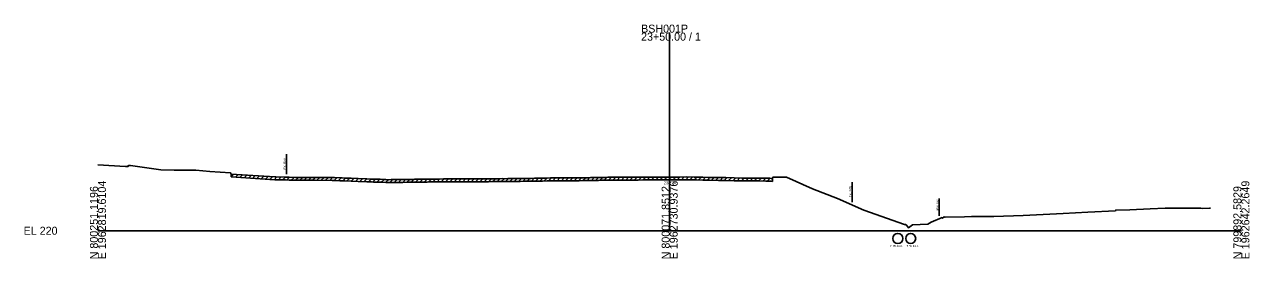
# Model space of a CAD drawing. Extents: x -26 to 1403, y -10 to 19587.
# Drawn here: x -25.7 to 402.8, y 7490.3 to 7572 of the extents above; entities that cross this region are included whole.
import ezdxf

# ---------------------------------------------------------------- set-up
doc = ezdxf.new("R2010")
doc.units = 0
for name, color, linetype in [('Default', 7, 'Continuous'), ('RD_EX_H2O', 7, 'Continuous'), ('RD_GPK_XS_Cell', 7, 'Continuous'), ('RD_XS_ExGround', 7, 'Continuous'), ('RD_XS_ExPaveRet', 7, 'Continuous'), ('RD_XS_ExRW', 7, 'Continuous'), ('RD_XS_NewRW', 7, 'Continuous'), ('RD_XS_TX_Elev_EX', 7, 'Continuous')]:
    doc.layers.add(name, color=color, linetype=linetype)

msp = doc.modelspace()

# ---------------------------------------------------------------- linework, layer by layer
at = {"layer": 'RD_EX_H2O'}
for centre in [(279.81, 7497.29), (284.31, 7497.29)]:
    msp.add_circle(centre, 1.75, dxfattribs=at)
at = {"layer": 'RD_GPK_XS_Cell'}
for p, q in [((200, 7500), (200, 7569.2)), ((0, 7500), (200, 7500)), ((200, 7500), (400, 7500))]:
    msp.add_line(p, q, dxfattribs=at)
at = {"layer": 'RD_XS_ExGround'}
msp.add_lwpolyline([(0, 7523.07), (9.67, 7522.48), (10.07, 7522.44), (10.48, 7522.4), (10.7, 7522.84), (11.4, 7522.77), (21.95, 7521.29), (26.69, 7521.14), (30.14, 7521.2), (34.27, 7521.13), (39.17, 7520.73), (46.42, 7520.22), (46.61, 7519.77), (61.88, 7518.82), (62.21, 7518.8), (65.56, 7518.76), (66.95, 7518.68), (69.11, 7518.63), (69.55, 7518.64), (72.11, 7518.65), (73.34, 7518.65), (73.64, 7518.64), (75.95, 7518.63), (81.95, 7518.59), (82.76, 7518.55), (84.58, 7518.48), (85.44, 7518.44), (86.42, 7518.41), (88.53, 7518.33), (91.02, 7518.21), (94.07, 7518.1), (95.65, 7518.05), (96.45, 7518.02), (98.73, 7517.96), (99.76, 7517.93), (100.76, 7517.86), (101.44, 7517.82), (101.8, 7517.83), (102.52, 7517.84), (103.98, 7517.85), (104.6, 7517.86), (105.34, 7517.87), (106.7, 7517.89), (108.12, 7517.92), (108.59, 7517.93), (109.56, 7517.94), (110.46, 7517.95), (110.91, 7517.96), (112.23, 7517.98), (113.71, 7518), (114.2, 7518.01), (115.18, 7518.02), (116.06, 7518.03), (116.49, 7518.04), (117.93, 7518.06), (119.28, 7518.07), (120.84, 7518.09), (121.67, 7518.09), (122.08, 7518.1), (123.28, 7518.1), (124.87, 7518.1), (125.47, 7518.09), (126.49, 7518.1), (127.26, 7518.09), (127.65, 7518.09), (128.58, 7518.1), (129.9, 7518.1), (130.93, 7518.1), (131.6, 7518.11), (133.16, 7518.11), (133.86, 7518.11), (135.51, 7518.12), (136.02, 7518.13), (136.59, 7518.12), (137.75, 7518.15), (138.8, 7518.16), (140.31, 7518.16), (141.59, 7518.19), (142.18, 7518.18), (143.4, 7518.21), (144.06, 7518.21), (144.38, 7518.22), (145.34, 7518.23), (146.97, 7518.23), (147.74, 7518.23), (148.96, 7518.26), (149.62, 7518.26), (149.93, 7518.27), (151.51, 7518.3), (152.7, 7518.31), (154.67, 7518.35), (155.53, 7518.36), (157.14, 7518.4), (158.35, 7518.43), (160.36, 7518.45), (161.07, 7518.45), (162.72, 7518.44), (163.9, 7518.45), (164.99, 7518.45), (166.58, 7518.46), (167.16, 7518.45), (167.54, 7518.45), (168.32, 7518.47), (169.5, 7518.51), (171.63, 7518.53), (172.28, 7518.54), (172.91, 7518.55), (175.07, 7518.59), (175.8, 7518.61), (177.27, 7518.64), (177.85, 7518.65), (178.42, 7518.66), (180.61, 7518.69), (182.87, 7518.69), (183.41, 7518.69), (185.1, 7518.7), (186.2, 7518.7), (188.48, 7518.71), (188.98, 7518.71), (190.68, 7518.74), (191.77, 7518.75), (192.57, 7518.75), (194.16, 7518.76), (194.56, 7518.76), (194.94, 7518.76), (197.31, 7518.75), (198.16, 7518.75), (200.19, 7518.74), (200.5, 7518.75), (202.93, 7518.76), (206.04, 7518.78), (208.52, 7518.76), (209.37, 7518.74), (211.55, 7518.7), (214.11, 7518.64), (217.05, 7518.6), (219.68, 7518.55), (222.56, 7518.47), (225.24, 7518.42), (228.02, 7518.38), (230.61, 7518.38), (230.95, 7518.38), (233.61, 7518.34), (235.02, 7518.33), (235.49, 7518.28), (235.93, 7518.25), (236.01, 7518.28), (236.11, 7518.73), (237.44, 7518.73), (240.89, 7518.74), (249.98, 7514.65), (258.73, 7511.22), (267.93, 7507.24), (282.15, 7502.2), (282.48, 7502.18), (282.91, 7501.78), (283.59, 7500.97), (284.94, 7502.04), (290.31, 7502.26), (291.44, 7503), (295.36, 7504.62), (295.46, 7504.37), (296.06, 7504.8), (296.4, 7504.79), (303.15, 7504.89), (305.55, 7504.92), (310.45, 7504.94), (313.44, 7504.94), (323.62, 7505.37), (337.61, 7506.07), (346.25, 7506.48), (355.94, 7507), (356.04, 7507.24), (360.97, 7507.33), (368.05, 7507.67), (373.35, 7507.83), (385.79, 7507.85), (386.56, 7507.78), (388.82, 7507.86), (389.16, 7507.92)], dxfattribs=at)
at = {"layer": 'RD_XS_ExPaveRet'}
for p, q in [((46.61, 7518.77), (46.61, 7519.77)), ((46.61, 7518.77), (47.55, 7519.71)), ((46.61, 7518.77), (61.88, 7517.82)), ((48.11, 7518.67), (49.05, 7519.61)), ((49.61, 7518.58), (50.55, 7519.52)), ((51.11, 7518.49), (52.05, 7519.43)), ((52.61, 7518.39), (53.55, 7519.33)), ((54.11, 7518.3), (55.05, 7519.24)), ((55.61, 7518.21), (56.55, 7519.15)), ((57.11, 7518.11), (58.05, 7519.06)), ((58.61, 7518.02), (59.55, 7518.96)), ((60.11, 7517.93), (61.05, 7518.87)), ((61.61, 7517.83), (62.57, 7518.79)), ((61.88, 7517.82), (62.21, 7517.8)), ((62.21, 7517.8), (65.56, 7517.76)), ((63.11, 7517.79), (64.1, 7518.78)), ((64.61, 7517.77), (65.6, 7518.76)), ((65.56, 7517.76), (66.95, 7517.68)), ((66.11, 7517.73), (67.06, 7518.68)), ((66.95, 7517.68), (69.11, 7517.63)), ((67.61, 7517.66), (68.59, 7518.64)), ((69.11, 7517.63), (70.12, 7518.64)), ((69.11, 7517.63), (69.55, 7517.64)), ((69.55, 7517.64), (72.11, 7517.65)), ((70.61, 7517.64), (71.62, 7518.65)), ((72.11, 7517.65), (73.11, 7518.65)), ((72.11, 7517.65), (73.34, 7517.65)), ((73.34, 7517.65), (73.64, 7517.64)), ((73.61, 7517.65), (74.61, 7518.64)), ((73.64, 7517.64), (75.95, 7517.63)), ((75.11, 7517.64), (76.11, 7518.63)), ((75.95, 7517.63), (81.95, 7517.59)), ((76.61, 7517.63), (77.61, 7518.62)), ((78.11, 7517.62), (79.11, 7518.61)), ((79.61, 7517.61), (80.61, 7518.6)), ((81.11, 7517.6), (82.1, 7518.58)), ((81.95, 7517.59), (82.76, 7517.55)), ((82.61, 7517.56), (83.57, 7518.52)), ((82.76, 7517.55), (84.58, 7517.48)), ((84.11, 7517.5), (85.07, 7518.46)), ((84.58, 7517.48), (85.44, 7517.44)), ((85.44, 7517.44), (86.42, 7517.41)), ((85.61, 7517.44), (86.58, 7518.4)), ((86.42, 7517.41), (88.53, 7517.33)), ((87.11, 7517.38), (88.08, 7518.35)), ((88.53, 7517.33), (91.02, 7517.21)), ((88.61, 7517.32), (89.57, 7518.28)), ((90.11, 7517.25), (91.07, 7518.21)), ((91.02, 7517.21), (94.07, 7517.1)), ((91.61, 7517.19), (92.58, 7518.15)), ((93.11, 7517.14), (94.08, 7518.1)), ((94.07, 7517.1), (95.65, 7517.05)), ((94.61, 7517.08), (95.58, 7518.05)), ((95.65, 7517.05), (96.45, 7517.02)), ((96.11, 7517.03), (97.08, 7518.01)), ((96.45, 7517.02), (98.73, 7516.96)), ((97.61, 7516.99), (98.58, 7517.96)), ((98.73, 7516.96), (99.76, 7516.93)), ((99.11, 7516.95), (100.07, 7517.9)), ((99.76, 7516.93), (100.76, 7516.86)), ((100.61, 7516.87), (101.57, 7517.83)), ((100.76, 7516.86), (101.44, 7516.82)), ((101.44, 7516.82), (101.8, 7516.83)), ((101.8, 7516.83), (102.52, 7516.84)), ((102.11, 7516.84), (103.12, 7517.85)), ((102.52, 7516.84), (103.98, 7516.85)), ((103.61, 7516.85), (104.62, 7517.86)), ((103.98, 7516.85), (104.6, 7516.86)), ((104.6, 7516.86), (105.34, 7516.87)), ((105.11, 7516.86), (106.13, 7517.88)), ((105.34, 7516.87), (106.7, 7516.89)), ((106.61, 7516.89), (107.63, 7517.91)), ((106.7, 7516.89), (108.12, 7516.92)), ((108.11, 7516.92), (109.13, 7517.94)), ((108.12, 7516.92), (108.59, 7516.93)), ((108.59, 7516.93), (109.56, 7516.94)), ((109.56, 7516.94), (110.46, 7516.95)), ((109.61, 7516.94), (110.63, 7517.96)), ((110.46, 7516.95), (110.91, 7516.96)), ((110.91, 7516.96), (112.23, 7516.98)), ((111.11, 7516.96), (112.13, 7517.98)), ((112.23, 7516.98), (113.71, 7517)), ((112.61, 7516.98), (113.63, 7518)), ((113.71, 7517), (114.2, 7517.01)), ((114.11, 7517), (115.13, 7518.02)), ((114.2, 7517.01), (115.18, 7517.02)), ((115.18, 7517.02), (116.06, 7517.03)), ((115.61, 7517.03), (116.63, 7518.04)), ((116.06, 7517.03), (116.49, 7517.04)), ((116.49, 7517.04), (117.93, 7517.06)), ((117.11, 7517.05), (118.13, 7518.06)), ((117.93, 7517.06), (119.28, 7517.07)), ((118.61, 7517.07), (119.62, 7518.08)), ((119.28, 7517.07), (120.84, 7517.09)), ((120.11, 7517.08), (121.12, 7518.09)), ((120.84, 7517.09), (121.67, 7517.09)), ((121.61, 7517.09), (122.62, 7518.1)), ((121.67, 7517.09), (122.08, 7517.1)), ((122.08, 7517.1), (123.28, 7517.1)), ((123.11, 7517.1), (124.11, 7518.1)), ((123.28, 7517.1), (124.87, 7517.1)), ((124.61, 7517.1), (125.61, 7518.09)), ((124.87, 7517.1), (125.47, 7517.09)), ((125.47, 7517.09), (126.49, 7517.1)), ((126.11, 7517.09), (127.11, 7518.09)), ((126.49, 7517.1), (127.26, 7517.09)), ((127.26, 7517.09), (127.65, 7517.09)), ((127.61, 7517.09), (128.62, 7518.1)), ((127.65, 7517.09), (128.58, 7517.1)), ((128.58, 7517.1), (129.9, 7517.1)), ((129.11, 7517.1), (130.11, 7518.1)), ((129.9, 7517.1), (130.93, 7517.1)), ((130.61, 7517.1), (131.62, 7518.11)), ((130.93, 7517.1), (131.6, 7517.11)), ((131.6, 7517.11), (133.16, 7517.11)), ((132.11, 7517.11), (133.12, 7518.11)), ((133.16, 7517.11), (133.86, 7517.11)), ((133.61, 7517.11), (134.62, 7518.12)), ((133.86, 7517.11), (135.51, 7517.12)), ((135.11, 7517.12), (136.12, 7518.13)), ((135.51, 7517.12), (136.02, 7517.13)), ((136.02, 7517.13), (136.59, 7517.12)), ((136.59, 7517.12), (137.75, 7517.15)), ((136.61, 7517.13), (137.64, 7518.15)), ((137.75, 7517.15), (138.8, 7517.16)), ((138.11, 7517.16), (139.12, 7518.16)), ((138.8, 7517.16), (140.31, 7517.16)), ((139.61, 7517.16), (140.62, 7518.17)), ((140.31, 7517.16), (141.59, 7517.19)), ((141.11, 7517.18), (142.12, 7518.18)), ((141.59, 7517.19), (142.18, 7517.18)), ((142.18, 7517.18), (143.4, 7517.21)), ((142.61, 7517.19), (143.63, 7518.21)), ((143.4, 7517.21), (144.06, 7517.21)), ((144.06, 7517.21), (144.38, 7517.22)), ((144.11, 7517.21), (145.12, 7518.23)), ((144.38, 7517.22), (145.34, 7517.23)), ((145.34, 7517.23), (146.97, 7517.23)), ((145.61, 7517.23), (146.61, 7518.23)), ((146.97, 7517.23), (147.74, 7517.23)), ((147.11, 7517.23), (148.12, 7518.24)), ((147.74, 7517.23), (148.96, 7517.26)), ((148.61, 7517.25), (149.62, 7518.26)), ((148.96, 7517.26), (149.62, 7517.26)), ((149.62, 7517.26), (149.93, 7517.27)), ((149.93, 7517.27), (151.51, 7517.3)), ((150.11, 7517.28), (151.13, 7518.3)), ((151.51, 7517.3), (152.7, 7517.31)), ((151.61, 7517.3), (152.61, 7518.31)), ((152.7, 7517.31), (154.67, 7517.35)), ((153.11, 7517.31), (154.13, 7518.34)), ((154.61, 7517.35), (155.63, 7518.36)), ((154.67, 7517.35), (155.53, 7517.36)), ((155.53, 7517.36), (157.14, 7517.4)), ((156.11, 7517.38), (157.14, 7518.4)), ((157.14, 7517.4), (158.35, 7517.43)), ((157.61, 7517.42), (158.63, 7518.44)), ((158.35, 7517.43), (160.36, 7517.45)), ((159.11, 7517.44), (160.12, 7518.44)), ((160.36, 7517.45), (161.07, 7517.45)), ((160.61, 7517.45), (161.61, 7518.45)), ((161.07, 7517.45), (162.72, 7517.44)), ((162.11, 7517.45), (163.11, 7518.45)), ((162.72, 7517.44), (163.9, 7517.45)), ((163.61, 7517.45), (164.61, 7518.45)), ((163.9, 7517.45), (164.99, 7517.45)), ((164.99, 7517.45), (166.58, 7517.46)), ((165.11, 7517.45), (166.12, 7518.46)), ((166.58, 7517.46), (167.16, 7517.45)), ((166.61, 7517.46), (167.6, 7518.45)), ((167.16, 7517.45), (167.54, 7517.45)), ((167.54, 7517.45), (168.32, 7517.47)), ((168.11, 7517.46), (169.15, 7518.5)), ((168.32, 7517.47), (169.5, 7517.51)), ((169.5, 7517.51), (171.63, 7517.53)), ((169.61, 7517.51), (170.62, 7518.52)), ((171.11, 7517.53), (172.12, 7518.54)), ((171.63, 7517.53), (172.28, 7517.54)), ((172.28, 7517.54), (172.91, 7517.55)), ((172.61, 7517.55), (173.63, 7518.57)), ((172.91, 7517.55), (175.07, 7517.59)), ((174.11, 7517.58), (175.13, 7518.6)), ((175.07, 7517.59), (175.8, 7517.61)), ((175.61, 7517.61), (176.63, 7518.63)), ((175.8, 7517.61), (177.27, 7517.64)), ((177.11, 7517.64), (178.13, 7518.66)), ((177.27, 7517.64), (177.85, 7517.65)), ((177.85, 7517.65), (178.42, 7517.66)), ((178.42, 7517.66), (180.61, 7517.69)), ((178.61, 7517.66), (179.63, 7518.67)), ((180.11, 7517.68), (181.12, 7518.69)), ((180.61, 7517.69), (182.87, 7517.69)), ((181.61, 7517.69), (182.61, 7518.69)), ((182.87, 7517.69), (183.41, 7517.69)), ((183.11, 7517.69), (184.11, 7518.69)), ((183.41, 7517.69), (185.1, 7517.7)), ((184.61, 7517.69), (185.62, 7518.7)), ((185.1, 7517.7), (186.2, 7517.7)), ((186.11, 7517.7), (187.12, 7518.7)), ((186.2, 7517.7), (188.48, 7517.71)), ((187.61, 7517.71), (188.62, 7518.71)), ((188.48, 7517.71), (188.98, 7517.71)), ((188.98, 7517.71), (190.68, 7517.74)), ((189.11, 7517.71), (190.13, 7518.73)), ((190.61, 7517.74), (191.62, 7518.75)), ((190.68, 7517.74), (191.77, 7517.75)), ((191.77, 7517.75), (192.57, 7517.75)), ((192.11, 7517.75), (193.12, 7518.76)), ((192.57, 7517.75), (194.16, 7517.76)), ((193.61, 7517.76), (194.61, 7518.76)), ((194.16, 7517.76), (194.56, 7517.76)), ((194.56, 7517.76), (194.94, 7517.76)), ((194.94, 7517.76), (197.31, 7517.75)), ((195.11, 7517.76), (196.11, 7518.75)), ((196.61, 7517.75), (197.61, 7518.75)), ((197.31, 7517.75), (198.16, 7517.75)), ((198.11, 7517.75), (199.11, 7518.75)), ((198.16, 7517.75), (200.19, 7517.74)), ((199.61, 7517.75), (200.61, 7518.75)), ((200.19, 7517.74), (200.5, 7517.75)), ((200.5, 7517.75), (202.93, 7517.76)), ((201.11, 7517.75), (202.12, 7518.76)), ((202.61, 7517.76), (203.62, 7518.77)), ((202.93, 7517.76), (206.04, 7517.78)), ((204.11, 7517.77), (205.12, 7518.78)), ((205.61, 7517.78), (206.61, 7518.78)), ((206.04, 7517.78), (208.52, 7517.76)), ((207.11, 7517.77), (208.1, 7518.77)), ((208.52, 7517.76), (209.37, 7517.74)), ((208.61, 7517.76), (209.59, 7518.74)), ((209.37, 7517.74), (211.55, 7517.7)), ((210.11, 7517.73), (211.09, 7518.71)), ((211.55, 7517.7), (214.11, 7517.64)), ((211.61, 7517.7), (212.59, 7518.67)), ((213.11, 7517.66), (214.09, 7518.64)), ((214.11, 7517.64), (217.05, 7517.6)), ((214.61, 7517.63), (215.6, 7518.62)), ((216.11, 7517.61), (217.1, 7518.6)), ((217.05, 7517.6), (219.68, 7517.55)), ((217.61, 7517.59), (218.59, 7518.57)), ((219.11, 7517.56), (220.09, 7518.54)), ((219.68, 7517.55), (222.56, 7517.47)), ((220.61, 7517.52), (221.59, 7518.5)), ((222.11, 7517.48), (223.09, 7518.46)), ((222.56, 7517.47), (225.24, 7517.42)), ((223.61, 7517.45), (224.59, 7518.43)), ((225.11, 7517.42), (226.1, 7518.41)), ((225.24, 7517.42), (228.02, 7517.38)), ((226.61, 7517.4), (227.6, 7518.39)), ((228.02, 7517.38), (230.61, 7517.38)), ((228.11, 7517.38), (229.11, 7518.38)), ((229.61, 7517.38), (230.61, 7518.38)), ((230.61, 7517.38), (230.95, 7517.38)), ((230.95, 7517.38), (233.61, 7517.34)), ((231.11, 7517.38), (232.1, 7518.36)), ((232.61, 7517.35), (233.6, 7518.34)), ((233.61, 7517.34), (235.02, 7517.33)), ((234.11, 7517.33), (235.1, 7518.32)), ((235.02, 7517.33), (235.49, 7517.28)), ((235.49, 7517.28), (235.93, 7517.25)), ((235.93, 7517.25), (236.01, 7517.47)), ((236.01, 7518.47), (236.01, 7517.47))]:
    msp.add_line(p, q, dxfattribs=at)
at = {"layer": 'RD_XS_ExRW'}
for p, q in [((66.01, 7519.74), (66.01, 7526.74)), ((263.83, 7510.01), (263.83, 7517.01))]:
    msp.add_line(p, q, dxfattribs=at)
at = {"layer": 'RD_XS_NewRW'}
msp.add_line((294.31, 7511.21), (294.31, 7505.21), dxfattribs=at)

# ---------------------------------------------------------------- texts
at = {"layer": 'Default'}
msp.add_text('-', height=0.0001, dxfattribs=at).set_placement((0, 7500))
at = {"layer": 'RD_EX_H2O'}
for p in [(277.12, 7494.34), (282.56, 7494.34)]:
    msp.add_text('PIPE EXT.', height=0.7, dxfattribs=at).set_placement(p)
at = {"layer": 'RD_GPK_XS_Cell'}
for s, p in [('23+50.00 / 1', (190, 7566.4)), ('BSH001P', (190, 7569.2)), ('EL 220', (-26, 7498.6))]:
    msp.add_text(s, height=2.8, dxfattribs=at).set_placement(p)
for s, p in [('E 1962819.6104', (2.8, 7490)), ('E 1962730.9376', (202.8, 7490)), ('E 1962642.2649', (402.8, 7490)), ('N 800251.1196', (0, 7490)), ('N 800071.8512', (200, 7490)), ('N 799892.5829', (400, 7490))]:
    msp.add_text(s, height=2.8, rotation=90, dxfattribs=at).set_placement(p)
at = {"layer": 'RD_XS_ExRW'}
for p in [(65.73, 7521.41), (263.58, 7511.68)]:
    msp.add_text('EX. R/W ', height=0.75, rotation=90, dxfattribs=at).set_placement(p)
at = {"layer": 'RD_XS_NewRW'}
msp.add_text('NEW R/W ', height=0.65, rotation=90, dxfattribs=at).set_placement((294.04, 7506.77))
at = {"layer": 'RD_XS_TX_Elev_EX'}
msp.add_text('238.74', height=1, dxfattribs=at).set_placement((197.95, 7516.24))

doc.saveas('drawing.dxf')
